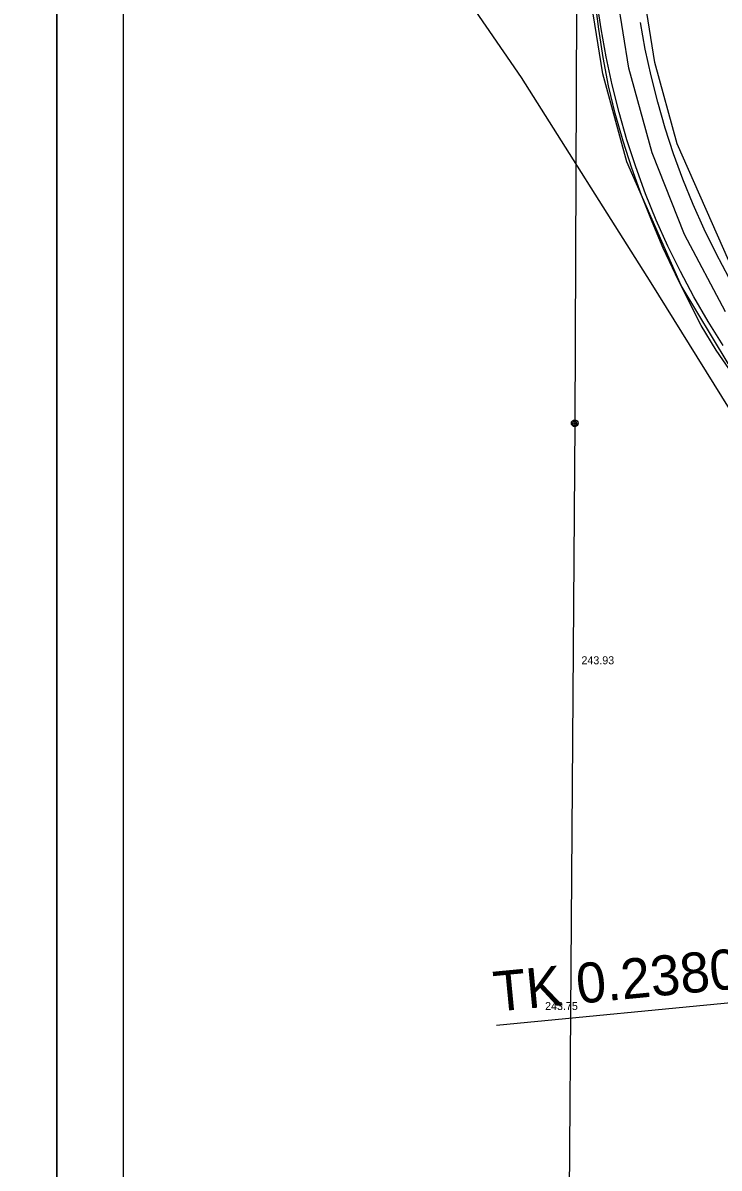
# Model space of a CAD drawing. Extents: x -555887 to -552101, y -1100251 to -1096546.
# Drawn here: x -554580.9 to -554528.7, y -1097721.3 to -1097635.4 of the extents above; entities that cross this region are included whole.
import ezdxf

# ---------------------------------------------------------------- set-up
doc = ezdxf.new("R2010")
doc.units = 0
for name, color, linetype in [('07_ELEKTRO', 7, 'Continuous'), ('PARCELY_cesty', 7, 'Continuous'), ('POLYGONY_SITUACE_PF_POPISY', 7, 'Continuous'), ('POLYGONY_SITUACE_PO', 7, 'Continuous'), ('ram_HC1', 7, 'Continuous'), ('vrstevnice', 7, 'Continuous'), ('Výškopis', 7, 'Continuous'), ('ZSST', 7, 'Continuous')]:
    doc.layers.add(name, color=color, linetype=linetype)

msp = doc.modelspace()

# ---------------------------------------------------------------- linework, layer by layer
at = {"layer": '07_ELEKTRO'}
msp.add_lwpolyline([(-554536.822, -1097177.881), (-554537.602, -1097278.405), (-554538.021, -1097373.3), (-554538.57, -1097463.608), (-554539.13, -1097565.858), (-554539.536, -1097665.448), (-554540.247, -1097764.017), (-554540.703, -1097863.048), (-554541.185, -1097956.002), (-554541.538, -1098055.43), (-554541.798, -1098155.569), (-554542.001, -1098255.51), (-554542.342, -1098356.724), (-554542.759, -1098456.405)], dxfattribs=at)
at = {"layer": 'PARCELY_cesty'}
for points in [[(-554512.1, -1097673.16), (-554518.741, -1097666.217), (-554524.725, -1097658.674), (-554527.983, -1097653.272), (-554531.841, -1097644.51), (-554533.518, -1097638.419), (-554534.524, -1097632.144), (-554534.841, -1097625.743), (-554532.595, -1097210.772)], [(-554515.01, -1097675.92), (-554521.761, -1097668.847), (-554528.018, -1097660.959), (-554531.54, -1097655.119), (-554535.62, -1097645.854), (-554537.433, -1097639.269), (-554538.509, -1097632.561), (-554538.841, -1097625.831), (-554536.72, -1097234.2)]]:
    msp.add_lwpolyline(points, dxfattribs=at)
at = {"layer": 'POLYGONY_SITUACE_PF_POPISY'}
msp.add_line((-554545.394, -1097710.544), (-554524.398, -1097708.526), dxfattribs=at)
at = {"layer": 'POLYGONY_SITUACE_PO'}
for p, q in [((-554535.475, -1097638.844), (-554536.516, -1097632.353)), ((-554537.734, -1097635.924), (-554538.004, -1097633.8)), ((-554537.56, -1097635.896), (-554537.864, -1097633.782)), ((-554534.239, -1097637.418), (-554534.598, -1097635.418)), ((-554534.239, -1097637.418), (-554534.598, -1097635.418)), ((-554534.239, -1097637.418), (-554534.598, -1097635.418)), ((-554537.406, -1097638.042), (-554537.734, -1097635.924)), ((-554537.182, -1097637.997), (-554537.56, -1097635.896)), ((-554533.81, -1097639.403), (-554534.239, -1097637.418)), ((-554533.81, -1097639.403), (-554534.239, -1097637.418)), ((-554533.81, -1097639.403), (-554534.239, -1097637.418)), ((-554537.012, -1097640.15), (-554537.406, -1097638.042)), ((-554536.732, -1097640.085), (-554537.182, -1097637.997)), ((-554533.73, -1097645.182), (-554535.475, -1097638.844)), ((-554533.311, -1097641.372), (-554533.81, -1097639.403)), ((-554533.311, -1097641.372), (-554533.81, -1097639.403)), ((-554533.311, -1097641.372), (-554533.81, -1097639.403)), ((-554536.5, -1097642.234), (-554537.012, -1097640.15)), ((-554536.208, -1097642.155), (-554536.732, -1097640.085)), ((-554532.75, -1097643.324), (-554533.311, -1097641.372)), ((-554532.75, -1097643.324), (-554533.311, -1097641.372)), ((-554532.75, -1097643.324), (-554533.311, -1097641.372)), ((-554535.912, -1097644.297), (-554536.5, -1097642.234)), ((-554535.617, -1097644.206), (-554536.208, -1097642.155)), ((-554532.118, -1097645.254), (-554532.75, -1097643.324)), ((-554532.118, -1097645.254), (-554532.75, -1097643.324)), ((-554532.118, -1097645.254), (-554532.75, -1097643.324)), ((-554535.24, -1097646.335), (-554535.912, -1097644.297)), ((-554534.953, -1097646.236), (-554535.617, -1097644.206)), ((-554531.302, -1097651.292), (-554533.73, -1097645.182)), ((-554531.419, -1097647.161), (-554532.118, -1097645.254)), ((-554531.419, -1097647.161), (-554532.118, -1097645.254)), ((-554531.419, -1097647.161), (-554532.118, -1097645.254)), ((-554534.519, -1097648.357), (-554535.24, -1097646.335)), ((-554534.218, -1097648.241), (-554534.953, -1097646.236)), ((-554530.654, -1097649.042), (-554531.419, -1097647.161)), ((-554530.654, -1097649.042), (-554531.419, -1097647.161)), ((-554530.654, -1097649.042), (-554531.419, -1097647.161)), ((-554533.738, -1097650.356), (-554534.519, -1097648.357)), ((-554533.414, -1097650.218), (-554534.218, -1097648.241)), ((-554529.825, -1097650.896), (-554530.654, -1097649.042)), ((-554529.825, -1097650.896), (-554530.654, -1097649.042)), ((-554529.825, -1097650.896), (-554530.654, -1097649.042)), ((-554532.896, -1097652.333), (-554533.738, -1097650.356)), ((-554532.542, -1097652.167), (-554533.414, -1097650.218)), ((-554528.934, -1097652.721), (-554529.825, -1097650.896)), ((-554528.934, -1097652.721), (-554529.825, -1097650.896)), ((-554528.934, -1097652.721), (-554529.825, -1097650.896)), ((-554528.221, -1097657.099), (-554531.302, -1097651.292)), ((-554531.983, -1097654.279), (-554532.896, -1097652.333)), ((-554531.606, -1097654.086), (-554532.542, -1097652.167)), ((-554527.979, -1097654.514), (-554528.934, -1097652.721)), ((-554527.979, -1097654.514), (-554528.934, -1097652.721)), ((-554527.979, -1097654.514), (-554528.934, -1097652.721)), ((-554531.015, -1097656.2), (-554531.983, -1097654.279)), ((-554530.601, -1097655.97), (-554531.606, -1097654.086)), ((-554530.053, -1097658.132), (-554531.015, -1097656.2)), ((-554529.533, -1097657.819), (-554530.601, -1097655.97)), ((-554528.399, -1097659.628), (-554529.533, -1097657.819)), ((-554528.92, -1097659.967), (-554530.053, -1097658.132)), ((-554527.705, -1097661.749), (-554528.92, -1097659.967))]:
    msp.add_line(p, q, dxfattribs=at)
at = {"layer": 'ram_HC1'}
for points in [[(-554578.37, -1097626.82), (-554215.29, -1097626.82), (-554215.29, -1097971.05), (-554578.37, -1097971.05)], [(-554573.37, -1097631.82), (-554220.29, -1097631.82), (-554220.29, -1097966.05), (-554573.37, -1097966.05)]]:
    msp.add_lwpolyline(points, close=True, dxfattribs=at)
for points in [[(-554578.37, -1097971.05), (-554215.29, -1097971.05), (-554215.29, -1097626.82), (-554578.37, -1097626.82), (-554578.37, -1097971.05)], [(-554573.37, -1097631.82), (-554220.29, -1097631.82), (-554220.29, -1097966.05), (-554573.37, -1097966.05), (-554573.37, -1097631.82)]]:
    msp.add_lwpolyline(points, dxfattribs=at)
at = {"layer": 'vrstevnice'}
msp.add_lwpolyline([(-554634.916, -1097540.372), (-554615.441, -1097559.428), (-554579.62, -1097595.396), (-554572.541, -1097601.891), (-554552.828, -1097626.043), (-554543.541, -1097639.532), (-554533.831, -1097654.917), (-554526.233, -1097667.142), (-554519.478, -1097676.205), (-554514.208, -1097681.355), (-554508.338, -1097685.503), (-554502.829, -1097689.561), (-554497.953, -1097691.364), (-554494.521, -1097692.266), (-554486.755, -1097692.627), (-554479.35, -1097690.282), (-554470.591, -1097686.856), (-554464.721, -1097683.79), (-554458.31, -1097680.093), (-554453.433, -1097674.863), (-554445.33, -1097667.351), (-554436.587, -1097659.868), (-554429.094, -1097653.099)], dxfattribs=at)
at = {"layer": 'ZSST'}
msp.add_lwpolyline([(-554536.822, -1097177.881), (-554537.602, -1097278.405), (-554538.021, -1097373.3), (-554538.57, -1097463.608), (-554539.13, -1097565.858), (-554539.536, -1097665.448), (-554540.247, -1097764.017), (-554540.703, -1097863.048)], dxfattribs=at)
for radius in [0.25, 0.158, 0.05]:
    msp.add_circle((-554539.536, -1097665.448), radius, dxfattribs=at)

# ---------------------------------------------------------------- texts
at = {"layer": 'POLYGONY_SITUACE_PF_POPISY'}
msp.add_text('TK 0.23803', height=3, rotation=5.4895, dxfattribs=at).set_placement((-554545.489, -1097709.549))
at = {"layer": 'Výškopis'}
for s, p in [('243.93', (-554539.03, -1097683.51)), ('243.75', (-554541.756, -1097709.42))]:
    msp.add_text(s, height=0.6, dxfattribs=at).set_placement(p)

doc.saveas('drawing.dxf')
